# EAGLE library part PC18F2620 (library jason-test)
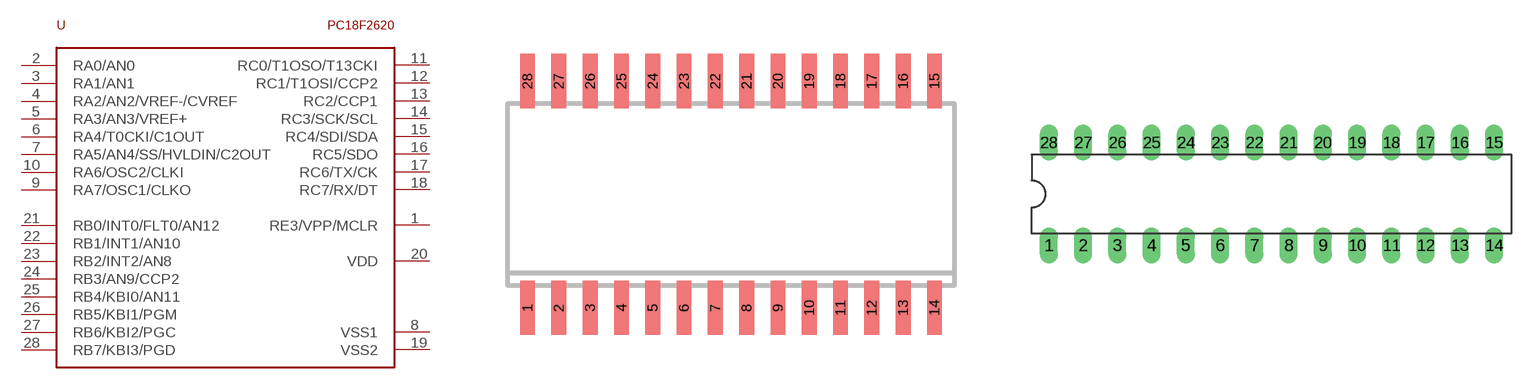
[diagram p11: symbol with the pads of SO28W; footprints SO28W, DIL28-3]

Designator prefix -

## PC18F2620SO  [SO28W]
1  RE3/VPP/MCLR
2  RA0/AN0
3  RA1/AN1
4  RA2/AN2/VREF-/CVREF
5  RA3/AN3/VREF+
6  RA4/T0CKI/C1OUT
7  RA5/AN4/SS/HVLDIN/C2OUT
8  VSS1  pwr
9  RA7/OSC1/CLKO
10  RA6/OSC2/CLKI
11  RC0/T1OSO/T13CKI
12  RC1/T1OSI/CCP2
13  RC2/CCP1
14  RC3/SCK/SCL
15  RC4/SDI/SDA
16  RC5/SDO
17  RC6/TX/CK
18  RC7/RX/DT
19  VSS2  pwr
20  VDD  pwr
21  RB0/INT0/FLT0/AN12
22  RB1/INT1/AN10
23  RB2/INT2/AN8
24  RB3/AN9/CCP2
25  RB4/KBI0/AN11
26  RB5/KBI1/PGM
27  RB6/KBI2/PGC
28  RB7/KBI3/PGD

## PC18F2620DIL  [DIL28-3]
Pads as for SO28W

## Footprint SO28W (pad centres in mm)
SMALL OUTLINE INTEGRATED CIRCUIT wide body 7.5 mm/JEDEC MO-119AB
smd 0.6 x 2.2: 1 -8.255,-4.6; 2 -6.985,-4.6; 3 -5.715,-4.6; 4 -4.445,-4.6; 5 -3.175,-4.6; 6 -1.905,-4.6; 7 -0.635,-4.6; 8 0.635,-4.6; 9 1.905,-4.6; 10 3.175,-4.6; 11 4.445,-4.6; 12 5.715,-4.6; 13 6.985,-4.6; 14 8.255,-4.6; 15 8.255,4.6; 16 6.985,4.6; 17 5.715,4.6; 18 4.445,4.6; 19 3.175,4.6; 20 1.905,4.6; 21 0.635,4.6; 22 -0.635,4.6; 23 -1.905,4.6; 24 -3.175,4.6; 25 -4.445,4.6; 26 -5.715,4.6; 27 -6.985,4.6; 28 -8.255,4.6

## Footprint DIL28-3 (pad centres in mm)
Dual In Line Package Small
drill 0.813 long: 1 -16.51,-3.81; 2 -13.97,-3.81; 3 -11.43,-3.81; 4 -8.89,-3.81; 5 -6.35,-3.81; 6 -3.81,-3.81; 7 -1.27,-3.81; 8 1.27,-3.81; 9 3.81,-3.81; 10 6.35,-3.81; 11 8.89,-3.81; 12 11.43,-3.81; 13 13.97,-3.81; 14 16.51,-3.81; 15 16.51,3.81; 16 13.97,3.81; 17 11.43,3.81; 18 8.89,3.81; 19 6.35,3.81; 20 3.81,3.81; 21 1.27,3.81; 22 -1.27,3.81; 23 -3.81,3.81; 24 -6.35,3.81; 25 -8.89,3.81; 26 -11.43,3.81; 27 -13.97,3.81; 28 -16.51,3.81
